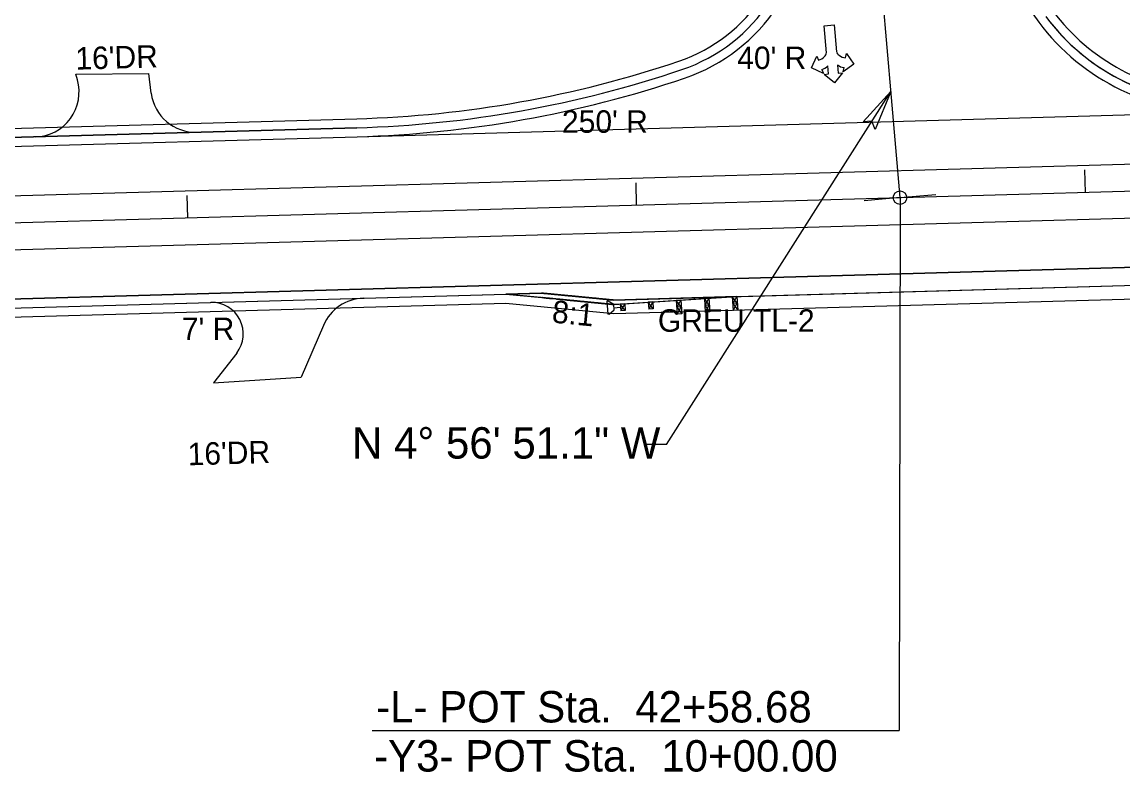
# Model space of a CAD drawing. Extents: x 1755545 to 1761252, y 736169 to 737766.
# Drawn here: x 1758746.3 to 1758991.6, y 736890.3 to 737057.4 of the extents above; entities that cross this region are included whole.
import ezdxf

# ---------------------------------------------------------------- set-up
doc = ezdxf.new("R2010")
doc.units = 0
for name, color, linetype in [('Exist Contamination Potential Cell', 7, 'Continuous'), ('Old_Level_1', 7, 'Continuous'), ('Prop Dimension', 7, 'Continuous'), ('Prop Guardrail', 7, 'Continuous'), ('Prop Guardrail Anchor Unit CELL', 7, 'Continuous'), ('Prop Horizontal Alignment', 7, 'Continuous'), ('Prop Horizontal Alignment Direction Label', 7, 'Continuous'), ('Prop Horizontal Alignment Station Label', 7, 'Continuous'), ('Prop Horizontal Alignment Tick Large', 7, 'Continuous'), ('Prop Horizontal Alignment Tick Small', 7, 'Continuous'), ('Prop Lane Arrow CELL', 7, 'Continuous'), ('Prop Lane Lines', 7, 'Continuous'), ('Prop Paved Shoulder', 7, 'Continuous'), ('Prop Shade Light', 7, 'Continuous'), ('Prop Terminator CELL', 7, 'Continuous'), ('Scratch_Level_4', 7, 'Continuous'), ('Scratch_Level_5', 7, 'Continuous'), ('Scratch_Level_6', 7, 'Continuous')]:
    doc.layers.add(name, color=color, linetype=linetype)

msp = doc.modelspace()

# ---------------------------------------------------------------- linework, layer by layer
at = {"layer": 'Exist Contamination Potential Cell'}
for p, q in [((1757498.66, 736960.29), (1760222.11, 737037.63)), ((1757497.77, 736994.28), (1758821.01, 737031.85))]:
    msp.add_line(p, q, dxfattribs=at)
for centre, radius, start, end in [((1759072.97, 737132.19), 125, 183.893, 216.7448), ((1758881.14, 737082.81), 40, 288.6709, 4.7221), ((1759012.87, 737087.32), 50, 216.7448, 271.6265), ((1758813.91, 737281.75), 250, 271.6265, 288.6709)]:
    msp.add_arc(centre, radius, start, end, dxfattribs=at)
at = {"layer": 'Old_Level_1'}
for p, q in [((1758758.32, 737045.82), (1758774.56, 737045.95)), ((1758758.68, 737044.56), (1758758.32, 737045.82)), ((1758775.13, 737041.55), (1758774.56, 737045.95)), ((1758813.5, 736989.82), (1758808.55, 736978.25)), ((1758794.17, 736983.64), (1758789.03, 736976.99)), ((1758789.03, 736976.99), (1758808.55, 736978.25))]:
    msp.add_line(p, q, dxfattribs=at)
for centre, radius, start, end in [((1758749.06, 737041.82), 10, 271.6265, 15.9173), ((1758785.05, 737042.84), 10, 187.3795, 271.6265), ((1758822.69, 736985.88), 10, 91.6265, 156.8216), ((1758788.63, 736987.92), 7, 322.3079, 91.6265)]:
    msp.add_arc(centre, radius, start, end, dxfattribs=at)
at = {"layer": 'Prop Guardrail'}
msp.add_line((1758905.56, 736996.24), (1759105.48, 737001.92), dxfattribs=at)
at = {"layer": 'Prop Guardrail Anchor Unit CELL'}
for p, q in [((1758880.11, 736994.6), (1758905.06, 736996.21)), ((1758893.09, 736995.44), (1758892.09, 736995.37)), ((1758892.09, 736995.37), (1758892.28, 736992.34)), ((1758893.18, 736993.92), (1758892.09, 736995.37)), ((1758893.09, 736995.44), (1758892.19, 736993.86)), ((1758893.09, 736995.44), (1758893.28, 736992.41)), ((1758899.32, 736995.84), (1758898.33, 736995.77)), ((1758898.33, 736995.77), (1758898.52, 736992.75)), ((1758899.42, 736994.32), (1758898.33, 736995.77)), ((1758899.32, 736995.84), (1758898.42, 736994.26)), ((1758899.32, 736995.84), (1758899.52, 736992.81)), ((1758905.56, 736996.24), (1758904.56, 736996.18)), ((1758904.56, 736996.18), (1758904.76, 736993.15)), ((1758905.66, 736994.73), (1758904.56, 736996.18)), ((1758905.56, 736996.24), (1758904.66, 736994.66)), ((1758905.56, 736996.24), (1758905.76, 736993.21)), ((1758876.92, 736995.24), (1758876.61, 736995.22)), ((1758876.61, 736995.22), (1758876.8, 736992.29)), ((1758878.15, 736994.46), (1758876.92, 736995.24)), ((1758877.11, 736992.31), (1758878.23, 736993.24)), ((1758879.62, 736994.56), (1758878.15, 736994.46)), ((1758878.23, 736993.24), (1758878.15, 736994.46)), ((1758878.19, 736993.74), (1758879.66, 736993.84)), ((1758880.61, 736994.63), (1758879.61, 736994.57)), ((1758879.61, 736994.57), (1758879.71, 736993.05)), ((1758880.71, 736993.12), (1758879.61, 736994.57)), ((1758880.61, 736994.63), (1758879.71, 736993.05)), ((1758880.71, 736993.12), (1758879.71, 736993.05)), ((1758880.61, 736994.63), (1758880.71, 736993.12)), ((1758886.85, 736995.04), (1758885.85, 736994.97)), ((1758885.85, 736994.97), (1758885.95, 736993.46)), ((1758886.95, 736993.52), (1758885.85, 736994.97)), ((1758886.85, 736995.04), (1758885.95, 736993.46)), ((1758886.95, 736993.52), (1758885.95, 736993.46)), ((1758886.85, 736995.04), (1758886.95, 736993.52)), ((1758893.18, 736993.92), (1758892.19, 736993.86)), ((1758892.19, 736993.86), (1758893.28, 736992.41)), ((1758892.28, 736992.34), (1758893.18, 736993.92)), ((1758899.42, 736994.32), (1758898.42, 736994.26)), ((1758898.42, 736994.26), (1758899.52, 736992.81)), ((1758898.52, 736992.75), (1758899.42, 736994.32)), ((1758905.66, 736994.73), (1758904.66, 736994.66)), ((1758904.66, 736994.66), (1758905.76, 736993.21)), ((1758904.76, 736993.15), (1758905.66, 736994.73)), ((1758905.76, 736993.21), (1758904.76, 736993.15)), ((1758877.11, 736992.31), (1758876.8, 736992.29)), ((1758893.28, 736992.41), (1758892.28, 736992.34)), ((1758899.52, 736992.81), (1758898.52, 736992.75))]:
    msp.add_line(p, q, dxfattribs=at)
at = {"layer": 'Prop Horizontal Alignment'}
for p, q in [((1758941.91, 737018.28), (1758936.77, 737077.73)), ((1757285.64, 736971.25), (1760282.69, 737056.35))]:
    msp.add_line(p, q, dxfattribs=at)
at = {"layer": 'Prop Horizontal Alignment Direction Label'}
for q in [(1758939.86, 737041.95), (1758885.09, 736963.25)]:
    msp.add_line((1758889.9, 736963.25), q, dxfattribs=at)
at = {"layer": 'Prop Horizontal Alignment Station Label'}
for p in [(1758941.91, 737018.28), (1758824.35, 736899.54)]:
    msp.add_line(p, (1758941.69, 736899.54), dxfattribs=at)
msp.add_circle((1758941.91, 737018.28), 1.5, dxfattribs=at)
at = {"layer": 'Prop Horizontal Alignment Tick Large'}
for q in [(1758933.94, 737017.59), (1758949.88, 737018.97)]:
    msp.add_line((1758941.91, 737018.28), q, dxfattribs=at)
at = {"layer": 'Prop Horizontal Alignment Tick Small'}
for p, q in [((1758983.21, 737019.45), (1758983.07, 737024.45)), ((1758883.25, 737016.62), (1758883.11, 737021.61)), ((1758783.29, 737013.78), (1758783.15, 737018.78))]:
    msp.add_line(p, q, dxfattribs=at)
at = {"layer": 'Prop Lane Arrow CELL'}
for p, q in [((1758925.02, 737056.55), (1758927.22, 737056.75)), ((1758927.22, 737056.75), (1758927.75, 737050.73)), ((1758925.55, 737050.57), (1758925.02, 737056.55)), ((1758922.18, 737047.17), (1758923.41, 737049.77)), ((1758923.41, 737049.77), (1758923.77, 737048.88)), ((1758929.79, 737049.41), (1758929.99, 737050.36)), ((1758929.99, 737050.36), (1758931.63, 737048)), ((1758924.85, 737045.94), (1758922.18, 737047.17)), ((1758924.49, 737046.84), (1758924.85, 737045.94)), ((1758925.97, 737045.83), (1758925.81, 737047.67)), ((1758928.01, 737047.83), (1758928.17, 737046.02)), ((1758931.63, 737048), (1758929.24, 737046.33)), ((1758929.24, 737046.33), (1758929.45, 737047.28)), ((1758925.05, 737045.74), (1758925.97, 737045.83)), ((1758927.29, 737043.84), (1758925.05, 737045.74)), ((1758929.09, 737046.1), (1758927.29, 737043.84)), ((1758928.17, 737046.02), (1758929.09, 737046.1))]:
    msp.add_line(p, q, dxfattribs=at)
for centre, radius, start, end in [((1758922.93, 737051.67), 2.91, 286.6966, 317.6268), ((1758923.92, 737050.9), 1.66, 314.1367, 348.9027), ((1758929.28, 737051.37), 1.66, 202.9925, 235.9904), ((1758930.12, 737052.31), 2.91, 232.5003, 263.713), ((1758923.67, 737049.63), 2.91, 286.3274, 317.2171), ((1758929.75, 737050.17), 2.91, 233.3068, 264.0832)]:
    msp.add_arc(centre, radius, start, end, dxfattribs=at)
at = {"layer": 'Prop Lane Lines'}
for p, q in [((1757285.47, 736977.25), (1760207.53, 737060.22)), ((1757285.81, 736965.25), (1760207.87, 737048.23)), ((1758821.01, 737031.85), (1759014.29, 737037.34))]:
    msp.add_line(p, q, dxfattribs=at)
at = {"layer": 'Prop Paved Shoulder'}
for p, q in [((1757497.71, 736996.28), (1758820.95, 737033.85)), ((1758905.56, 736996.24), (1759105.48, 737001.92)), ((1757498.72, 736958.29), (1758854.08, 736996.78)), ((1758878.15, 736994.46), (1758854.08, 736996.78)), ((1758878.15, 736994.46), (1758905.56, 736996.24))]:
    msp.add_line(p, q, dxfattribs=at)
for centre, radius, start, end in [((1758881.14, 737082.81), 38, 288.6709, 4.7237), ((1759012.87, 737087.32), 48, 216.7448, 268.3507), ((1758813.91, 737281.75), 248, 271.6265, 288.6709)]:
    msp.add_arc(centre, radius, start, end, dxfattribs=at)
msp.add_spline([(1758878.15, 736994.46), (1758877.93, 736994.48), (1758877.71, 736994.5), (1758877.5, 736994.53), (1758877.28, 736994.55), (1758877.06, 736994.57), (1758876.85, 736994.59), (1758876.63, 736994.61), (1758876.41, 736994.63), (1758876.19, 736994.65), (1758875.98, 736994.67), (1758875.76, 736994.69), (1758875.54, 736994.71), (1758875.33, 736994.73), (1758875.11, 736994.75), (1758874.89, 736994.78), (1758874.68, 736994.8), (1758874.46, 736994.82), (1758874.24, 736994.84), (1758874.03, 736994.86), (1758873.81, 736994.88), (1758873.59, 736994.9), (1758873.38, 736994.92), (1758873.16, 736994.94), (1758872.94, 736994.96), (1758872.72, 736994.98), (1758872.51, 736995.01), (1758872.29, 736995.03), (1758872.07, 736995.05), (1758871.86, 736995.07), (1758871.64, 736995.09), (1758871.42, 736995.11), (1758871.21, 736995.13), (1758870.99, 736995.15), (1758870.77, 736995.17), (1758870.56, 736995.19), (1758870.34, 736995.21), (1758870.12, 736995.23), (1758869.9, 736995.26), (1758869.69, 736995.28), (1758869.47, 736995.3), (1758869.25, 736995.32), (1758869.04, 736995.34), (1758868.82, 736995.36), (1758868.6, 736995.38), (1758868.39, 736995.4), (1758868.17, 736995.42), (1758867.95, 736995.44), (1758867.74, 736995.46), (1758867.52, 736995.49), (1758867.3, 736995.51), (1758867.09, 736995.53), (1758866.87, 736995.55), (1758866.65, 736995.57), (1758866.43, 736995.59), (1758866.22, 736995.61), (1758866, 736995.63), (1758865.78, 736995.65), (1758865.57, 736995.67), (1758865.35, 736995.69), (1758865.13, 736995.72), (1758864.92, 736995.74), (1758864.7, 736995.76), (1758864.48, 736995.78), (1758864.27, 736995.8), (1758864.05, 736995.82), (1758863.83, 736995.84), (1758863.62, 736995.86), (1758863.4, 736995.88), (1758863.18, 736995.9), (1758862.96, 736995.92), (1758862.75, 736995.94), (1758862.53, 736995.97), (1758862.1, 736996.01)], degree=3, dxfattribs=at)
at = {"layer": 'Prop Shade Light'}
for p, q in [((1760222.11, 737037.63), (1757498.66, 736960.29)), ((1758820.95, 737033.85), (1757497.71, 736996.28)), ((1757497.77, 736994.28), (1758821.01, 737031.85)), ((1758878.1, 736995.46), (1759105.48, 737001.92)), ((1757498.72, 736958.29), (1758862.05, 736997.01)), ((1758862.05, 736997.01), (1758854.08, 736996.78)), ((1758854.08, 736996.78), (1758862.1, 736996.01)), ((1758862.1, 736996.01), (1758862.2, 736996)), ((1758862.2, 736996), (1758862.59, 736995.96)), ((1758868.52, 736995.39), (1758868.81, 736995.36)), ((1758905.56, 736996.24), (1758878.1, 736995.46)), ((1758878.15, 736994.46), (1758905.56, 736996.24)), ((1758875.53, 736994.71), (1758875.81, 736994.69)), ((1758877.84, 736994.49), (1758878.15, 736994.46))]:
    msp.add_line(p, q, dxfattribs=at)
for points in [[(1758864.06, 736995.82), (1758865.23, 736995.71), (1758865.4, 736995.69)], [(1758866.79, 736995.56), (1758866.89, 736995.55), (1758867.28, 736995.51), (1758867.45, 736995.49)], [(1758870.36, 736995.21), (1758870.76, 736995.17), (1758871.18, 736995.13), (1758871.25, 736995.13)], [(1758872.66, 736994.99), (1758872.8, 736994.98), (1758872.81, 736994.98)], [(1758876.28, 736994.64), (1758876.61, 736994.61), (1758876.64, 736994.61), (1758877.02, 736994.57)]]:
    msp.add_lwpolyline(points, dxfattribs=at)
for centre, radius, start, end in [((1759072.97, 737132.19), 125, 183.893, 216.7448), ((1758881.14, 737082.81), 40, 288.6709, 4.7221), ((1758881.14, 737082.81), 38, 288.6709, 4.7237), ((1759012.87, 737087.32), 50, 216.7448, 271.6265), ((1759012.87, 737087.32), 48, 216.7448, 271.6265), ((1758813.91, 737281.75), 248, 271.6265, 288.6709), ((1758813.91, 737281.75), 250, 271.6265, 288.6709)]:
    msp.add_arc(centre, radius, start, end, dxfattribs=at)
for points in [[(1758862.05, 736997.01), (1758862.49, 736996.96), (1758862.7, 736996.94), (1758862.92, 736996.92), (1758863.14, 736996.9), (1758863.35, 736996.88), (1758863.57, 736996.86), (1758863.79, 736996.84), (1758864, 736996.82), (1758864.22, 736996.8), (1758864.44, 736996.78), (1758864.65, 736996.76), (1758864.87, 736996.73), (1758865.09, 736996.71), (1758865.31, 736996.69), (1758865.52, 736996.67), (1758865.74, 736996.65), (1758865.96, 736996.63), (1758866.17, 736996.61), (1758866.39, 736996.59), (1758866.61, 736996.57), (1758866.82, 736996.55), (1758867.04, 736996.53), (1758867.26, 736996.5), (1758867.4, 736996.49)], [(1758867.4, 736996.49), (1758867.26, 736996.5), (1758867.04, 736996.53), (1758866.82, 736996.55), (1758866.61, 736996.57), (1758866.39, 736996.59), (1758866.17, 736996.61), (1758865.96, 736996.63), (1758865.74, 736996.65), (1758865.52, 736996.67), (1758865.31, 736996.69), (1758865.09, 736996.71), (1758864.87, 736996.73), (1758864.65, 736996.76), (1758864.44, 736996.78), (1758864.22, 736996.8), (1758864, 736996.82), (1758863.79, 736996.84), (1758863.57, 736996.86), (1758863.35, 736996.88), (1758863.14, 736996.9), (1758862.92, 736996.92), (1758862.7, 736996.94), (1758862.49, 736996.96), (1758862.05, 736997.01)], [(1758865.4, 736995.69), (1758865.57, 736995.67), (1758865.78, 736995.65), (1758866, 736995.63), (1758866.22, 736995.61), (1758866.43, 736995.59), (1758866.65, 736995.57), (1758866.79, 736995.56)], [(1758867.4, 736996.49), (1758867.47, 736996.48), (1758867.69, 736996.46), (1758867.91, 736996.44), (1758868.12, 736996.42), (1758868.34, 736996.4), (1758868.56, 736996.38), (1758868.78, 736996.36), (1758868.99, 736996.34), (1758869.21, 736996.32), (1758869.43, 736996.3), (1758869.64, 736996.28), (1758869.86, 736996.25), (1758870.08, 736996.23), (1758870.29, 736996.21), (1758870.51, 736996.19), (1758870.73, 736996.17), (1758870.94, 736996.15), (1758871.16, 736996.13), (1758871.38, 736996.11), (1758871.6, 736996.09), (1758871.81, 736996.07), (1758872.03, 736996.05), (1758872.25, 736996.02), (1758872.46, 736996), (1758872.68, 736995.98), (1758872.75, 736995.98)], [(1758872.75, 736995.98), (1758872.68, 736995.98), (1758872.46, 736996), (1758872.25, 736996.02), (1758872.03, 736996.05), (1758871.81, 736996.07), (1758871.6, 736996.09), (1758871.38, 736996.11), (1758871.16, 736996.13), (1758870.94, 736996.15), (1758870.73, 736996.17), (1758870.51, 736996.19), (1758870.29, 736996.21), (1758870.08, 736996.23), (1758869.86, 736996.25), (1758869.64, 736996.28), (1758869.43, 736996.3), (1758869.21, 736996.32), (1758868.99, 736996.34), (1758868.78, 736996.36), (1758868.56, 736996.38), (1758868.34, 736996.4), (1758868.12, 736996.42), (1758867.91, 736996.44), (1758867.69, 736996.46), (1758867.47, 736996.48), (1758867.4, 736996.49)], [(1758872.75, 736995.98), (1758872.9, 736995.96), (1758873.11, 736995.94), (1758873.33, 736995.92), (1758873.55, 736995.9), (1758873.76, 736995.88), (1758873.98, 736995.86), (1758874.2, 736995.84), (1758874.41, 736995.82), (1758874.63, 736995.79), (1758874.85, 736995.77), (1758875.07, 736995.75), (1758875.28, 736995.73), (1758875.5, 736995.71), (1758875.72, 736995.69), (1758875.93, 736995.67), (1758876.15, 736995.65), (1758876.37, 736995.63), (1758876.58, 736995.61), (1758876.8, 736995.59), (1758877.02, 736995.57), (1758877.23, 736995.54), (1758877.45, 736995.52), (1758877.67, 736995.5), (1758877.89, 736995.48), (1758878.1, 736995.46)], [(1758878.1, 736995.46), (1758877.89, 736995.48), (1758877.67, 736995.5), (1758877.45, 736995.52), (1758877.23, 736995.54), (1758877.02, 736995.57), (1758876.8, 736995.59), (1758876.58, 736995.61), (1758876.37, 736995.63), (1758876.15, 736995.65), (1758875.93, 736995.67), (1758875.72, 736995.69), (1758875.5, 736995.71), (1758875.28, 736995.73), (1758875.07, 736995.75), (1758874.85, 736995.77), (1758874.63, 736995.79), (1758874.41, 736995.82), (1758874.2, 736995.84), (1758873.98, 736995.86), (1758873.76, 736995.88), (1758873.55, 736995.9), (1758873.33, 736995.92), (1758873.11, 736995.94), (1758872.9, 736995.96), (1758872.75, 736995.98)], [(1758871.25, 736995.13), (1758871.42, 736995.11), (1758871.64, 736995.09), (1758871.86, 736995.07), (1758872.07, 736995.05), (1758872.29, 736995.03), (1758872.51, 736995.01), (1758872.66, 736994.99)]]:
    msp.add_spline(points, degree=3, dxfattribs=at)
for points in [[(1758862.59, 736995.96), (1758862.65, 736995.95), (1758862.7, 736995.95), (1758862.75, 736995.94), (1758862.82, 736995.94), (1758862.89, 736995.93), (1758862.96, 736995.92), (1758863.04, 736995.92), (1758863.11, 736995.91), (1758863.18, 736995.9), (1758863.25, 736995.9), (1758863.33, 736995.89), (1758863.4, 736995.88), (1758863.47, 736995.88), (1758863.54, 736995.87), (1758863.62, 736995.86), (1758863.69, 736995.85), (1758863.76, 736995.85), (1758863.83, 736995.84), (1758863.9, 736995.83), (1758863.98, 736995.83), (1758864.05, 736995.82), (1758864.05, 736995.82), (1758864.06, 736995.82), (1758864.06, 736995.82)], [(1758867.45, 736995.49), (1758867.47, 736995.49), (1758867.5, 736995.49), (1758867.52, 736995.49), (1758867.59, 736995.48), (1758867.66, 736995.47), (1758867.74, 736995.46), (1758867.81, 736995.46), (1758867.88, 736995.45), (1758867.95, 736995.44), (1758868.03, 736995.44), (1758868.1, 736995.43), (1758868.17, 736995.42), (1758868.24, 736995.42), (1758868.31, 736995.41), (1758868.39, 736995.4), (1758868.43, 736995.4), (1758868.48, 736995.39), (1758868.52, 736995.39)], [(1758868.81, 736995.36), (1758868.81, 736995.36), (1758868.82, 736995.36), (1758868.82, 736995.36), (1758868.89, 736995.35), (1758868.97, 736995.35), (1758869.04, 736995.34), (1758869.11, 736995.33), (1758869.18, 736995.33), (1758869.25, 736995.32), (1758869.33, 736995.31), (1758869.4, 736995.3), (1758869.47, 736995.3), (1758869.54, 736995.29), (1758869.62, 736995.28), (1758869.69, 736995.28), (1758869.76, 736995.27), (1758869.83, 736995.26), (1758869.9, 736995.26), (1758869.98, 736995.25), (1758870.05, 736995.24), (1758870.12, 736995.23), (1758870.19, 736995.23), (1758870.27, 736995.22), (1758870.34, 736995.21), (1758870.35, 736995.21), (1758870.36, 736995.21), (1758870.36, 736995.21)], [(1758872.81, 736994.98), (1758872.86, 736994.97), (1758872.9, 736994.97), (1758872.94, 736994.96), (1758873.01, 736994.96), (1758873.09, 736994.95), (1758873.16, 736994.94), (1758873.23, 736994.94), (1758873.3, 736994.93), (1758873.38, 736994.92), (1758873.45, 736994.91), (1758873.52, 736994.91), (1758873.59, 736994.9), (1758873.66, 736994.89), (1758873.74, 736994.89), (1758873.81, 736994.88), (1758873.88, 736994.87), (1758873.95, 736994.87), (1758874.03, 736994.86), (1758874.1, 736994.85), (1758874.17, 736994.85), (1758874.24, 736994.84), (1758874.32, 736994.83), (1758874.39, 736994.82), (1758874.46, 736994.82), (1758874.53, 736994.81), (1758874.6, 736994.8), (1758874.68, 736994.8), (1758874.75, 736994.79), (1758874.82, 736994.78), (1758874.89, 736994.78), (1758874.97, 736994.77), (1758875.04, 736994.76), (1758875.11, 736994.75), (1758875.18, 736994.75), (1758875.26, 736994.74), (1758875.33, 736994.73), (1758875.4, 736994.73), (1758875.46, 736994.72), (1758875.53, 736994.71)], [(1758875.81, 736994.69), (1758875.86, 736994.68), (1758875.92, 736994.68), (1758875.98, 736994.67), (1758876.05, 736994.66), (1758876.12, 736994.66), (1758876.19, 736994.65), (1758876.22, 736994.65), (1758876.25, 736994.64), (1758876.28, 736994.64)], [(1758877.02, 736994.57), (1758877.03, 736994.57), (1758877.05, 736994.57), (1758877.06, 736994.57), (1758877.13, 736994.56), (1758877.21, 736994.55), (1758877.28, 736994.55), (1758877.35, 736994.54), (1758877.42, 736994.53), (1758877.5, 736994.53), (1758877.57, 736994.52), (1758877.64, 736994.51), (1758877.71, 736994.5), (1758877.75, 736994.5), (1758877.79, 736994.5), (1758877.84, 736994.49)]]:
    msp.add_open_spline(points, degree=3, dxfattribs=at)
at = {"layer": 'Prop Terminator CELL'}
msp.add_lwpolyline([(1758933.73, 737035.18), (1758939.86, 737041.95), (1758936.36, 737033.45), (1758935.63, 737035.28)], close=True, dxfattribs=at)
at = {"layer": 'Scratch_Level_5'}
for p, q in [((1758905.56, 736996.24), (1759105.48, 737001.92)), ((1758878.1, 736995.45), (1758905.56, 736996.24))]:
    msp.add_line(p, q, dxfattribs=at)
at = {"layer": 'Scratch_Level_6'}
for p, q in [((1757497.65, 736998.28), (1758820.89, 737035.85)), ((1758878.19, 736992.46), (1759105.57, 736998.92)), ((1757498.78, 736956.29), (1758854.11, 736994.78)), ((1758854.11, 736994.78), (1758878.19, 736992.46))]:
    msp.add_line(p, q, dxfattribs=at)
for centre, radius, start, end in [((1758881.14, 737082.81), 36, 288.6709, 4.7221), ((1759012.87, 737087.32), 46, 216.7448, 267.0271), ((1758813.91, 737281.75), 246, 271.6265, 288.6709)]:
    msp.add_arc(centre, radius, start, end, dxfattribs=at)

# ---------------------------------------------------------------- texts
at = {"layer": 'Prop Dimension'}
msp.add_text("40' R", height=5, dxfattribs=at).set_placement((1758905.65, 737046.93))
for s, rotation, p in [("250' R", 360, (1758866.62, 737032.73)), ('8:1', 354.5015, (1758864.24, 736990.46)), ("7' R", 360, (1758781.95, 736986.54))]:
    msp.add_text(s, height=5, rotation=rotation, dxfattribs=at).set_placement(p)
at = {"layer": 'Prop Guardrail Anchor Unit CELL'}
msp.add_text('GREU TL-2', height=5, rotation=360, dxfattribs=at).set_placement((1758887.98, 736988.39))
at = {"layer": 'Prop Horizontal Alignment Direction Label'}
msp.add_text('N 4%%d 56\' 51.1" W', height=7, rotation=360, dxfattribs=at).set_placement((1758819.86, 736960.13))
at = {"layer": 'Prop Horizontal Alignment Station Label'}
msp.add_text('-L- POT Sta.  42+58.68', height=7, dxfattribs=at).set_placement((1758825.21, 736901.33))
msp.add_text('-Y3- POT Sta.  10+00.00', height=7, rotation=360, dxfattribs=at).set_placement((1758824.77, 736890.39))
at = {"layer": 'Scratch_Level_4'}
for p in [(1758758.3, 737046.78), (1758783.31, 736958.62)]:
    msp.add_text("16'DR", height=5, rotation=1.6265, dxfattribs=at).set_placement(p)

doc.saveas('drawing.dxf')
